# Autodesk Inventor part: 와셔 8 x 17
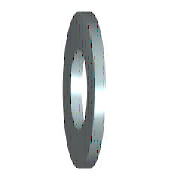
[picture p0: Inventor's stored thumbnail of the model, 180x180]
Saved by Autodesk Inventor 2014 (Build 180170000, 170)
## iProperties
IsCustomPart: 1
Created: 2012-02
Part Number: 와셔 8 x 17
Material: 강철, 연강
Description: 평면 와셔
Document SubType Name: Modeling
Standard: KS B 1326
Designer: mduedu
Standards Organization: KS
Language: ko-KR
Size Designation: 8x17
Categories: <MemberInstance><Categories><Category DisplayName="조임쇠" InternalName="e4da775c-781d-43d5-af7c-5136215cf5a6" Mnemonic="FSTN"><Category DisplayName="와셔" InternalN
Density: 7.86 g/cm^3
Mass: 2.15757 g
Surface Area: 4.70799 cm^2
Volume: 0.2745 cm^3
Appearance: 주황색
Author: mduedu
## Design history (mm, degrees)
sketch "스케치"
  geometry: C1 r 8.5 at (0, 0); C2 r 4.2 at (0, 0); 1 further point
  constraints: 2 centre point, 2 coincident
  dimensions: "d0" = 8.4 diameter of C2 (= SD1); "d1" = 17 diameter of C1 (= SD2)
extrude "본체" new body sketch "스케치" distance "d2" = 1.6 (= SD); taper "d3" = 0 deg
workaxis "Work Axis1"
workplane "Work Plane1"
body "Solid1"
other parameters: "SD1" = 8.4 [user parameter; used in 1 equation term], "SD2" = 17 [user parameter; used in 1 equation term], "SD" = 1.6 [user parameter; used in 1 equation term], "d4" = 0, "d5" = 0, "d6" = 0, "d7" = 0, "NND" = 8 [user parameter]
